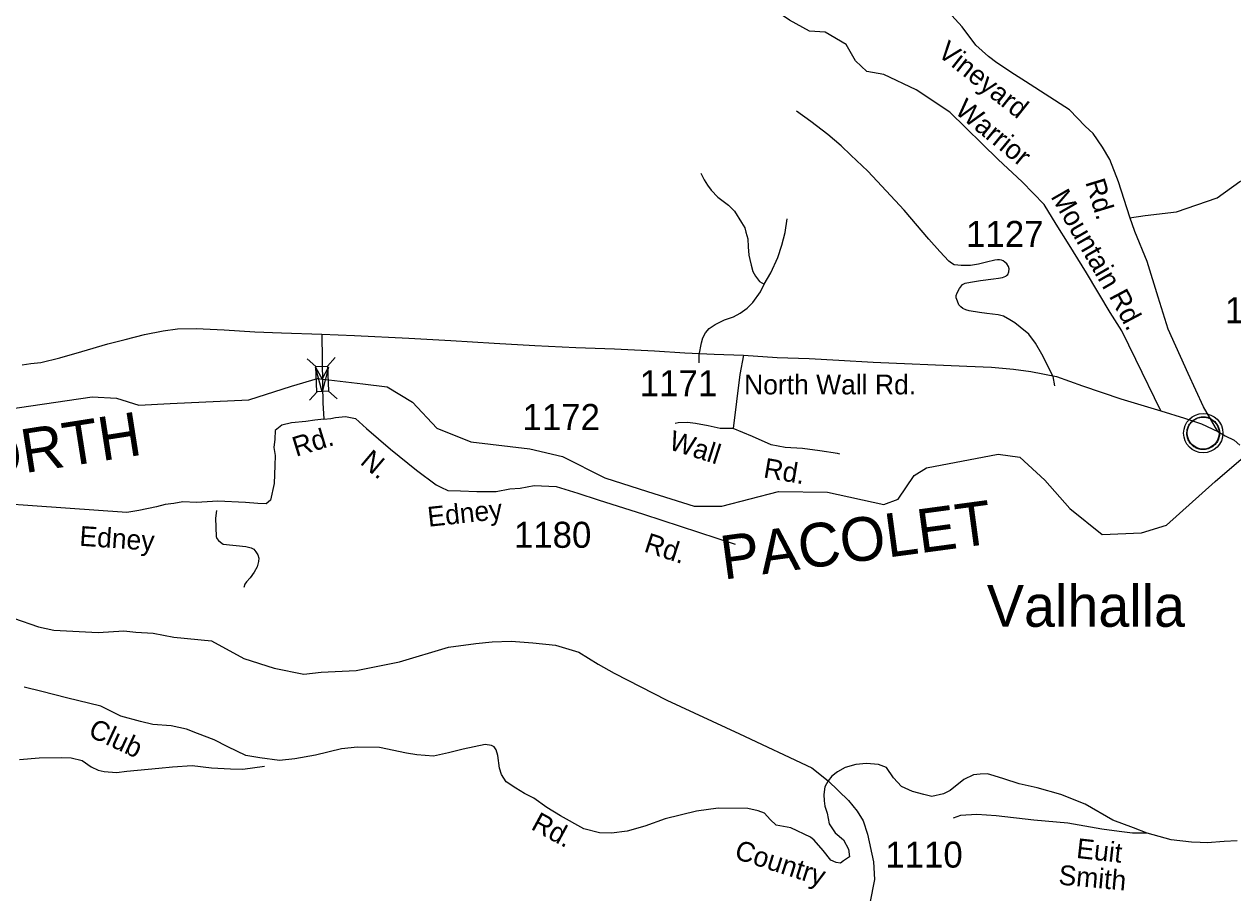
# Model space of a CAD drawing. Extents: x 990631 to 1056237, y 535999 to 585651.
# Drawn here: x 1021960 to 1027764, y 550123 to 554294 of the extents above; entities that cross this region are included whole.
import ezdxf

# ---------------------------------------------------------------- set-up
doc = ezdxf.new("R2010")
doc.units = 0
for name, color, linetype in [('Exist Civil Demographics Community CELL', 7, 'Continuous'), ('Exist Civil Demographics Community Label', 7, 'Continuous'), ('Exist Hydrographic River Shore', 7, 'Continuous'), ('Exist Hydrographic River Shore Label', 7, 'Continuous'), ('Exist Railroad Mainline', 7, 'Continuous'), ('Exist Road Non-System Type 51', 7, 'Continuous'), ('Exist Road Primary US Attributed', 7, 'Continuous'), ('Exist Road Secondary Structure Standard Bridge Attributed CELL', 7, 'Continuous'), ('Exist Road Secondary Structure Standard Bridge CELL', 7, 'Continuous'), ('Exist Road Secondary Type 41 Attributed', 7, 'Continuous'), ('Exist Road Secondary Type 51 Attributed', 7, 'Continuous'), ('Exist Road Secondary Type 51 Label', 7, 'Continuous'), ('Exist Road Secondary Type 51 Number Label', 7, 'Continuous')]:
    doc.layers.add(name, color=color, linetype=linetype)

msp = doc.modelspace()

# ---------------------------------------------------------------- linework, layer by layer
at = {"layer": 'Exist Civil Demographics Community CELL'}
msp.add_lwpolyline([(1027544.6, 552342.9), (1027545.6, 552348.5), (1027547.4, 552355.1), (1027550.3, 552362.3), (1027553.2, 552368), (1027556.5, 552373.8), (1027560.3, 552378.9), (1027564.3, 552383.3), (1027568.9, 552387.9), (1027574.4, 552392.4), (1027579.8, 552396.1), (1027584.7, 552399), (1027589.7, 552401.4), (1027595.2, 552403.7), (1027600.8, 552405.5), (1027605.2, 552406.7), (1027610, 552407.4), (1027614.1, 552408.1), (1027620.5, 552408.4), (1027624.9, 552408.3), (1027630.6, 552408), (1027635.5, 552407.3), (1027640.4, 552406.3), (1027645.4, 552404.9), (1027650.6, 552403), (1027657.2, 552400.1), (1027663.5, 552396.6), (1027668.6, 552393), (1027673.7, 552389), (1027677, 552385.9), (1027681.2, 552381.5), (1027685, 552376.8), (1027688.1, 552372.2), (1027691.2, 552367.2), (1027693.7, 552362), (1027695.7, 552357), (1027697.3, 552352), (1027698.6, 552347.4), (1027699.7, 552341.4), (1027700.3, 552336.7), (1027700.5, 552330.7), (1027700.4, 552324.9), (1027699.8, 552319.2), (1027698.9, 552313.7), (1027697.2, 552307.5), (1027695.3, 552301.7), (1027693, 552296.6), (1027689.9, 552290.6), (1027686.6, 552285.3), (1027683.1, 552280.6), (1027678.9, 552275.9), (1027673.6, 552270.9), (1027668.6, 552266.8), (1027663.6, 552263.4), (1027659.3, 552260.8), (1027652.5, 552257.6), (1027645.3, 552254.9), (1027639.4, 552253.4), (1027632.8, 552252.1), (1027628.3, 552251.7), (1027623.8, 552251.4), (1027618.3, 552251.4), (1027614, 552251.8), (1027608.3, 552252.6), (1027602.4, 552253.9), (1027597.8, 552255.2), (1027592.7, 552257), (1027588.1, 552259), (1027584.2, 552261.3), (1027577.4, 552265.3), (1027571.8, 552269.6), (1027566.9, 552274.1), (1027562.4, 552279), (1027559.2, 552282.9), (1027556.2, 552287.1), (1027552.2, 552294.2), (1027550.4, 552297.7), (1027548.7, 552301.8), (1027546.1, 552309.9), (1027544.6, 552317), (1027543.9, 552322.2), (1027543.6, 552328.5), (1027543.5, 552333.2), (1027544.1, 552339.6)], close=True, dxfattribs=at)
for centre, radius in [((1027622.2, 552330.5), 94.3), ((1027621.9, 552330.8), 76.7)]:
    msp.add_circle(centre, radius, dxfattribs=at)
at = {"layer": 'Exist Hydrographic River Shore'}
msp.add_lwpolyline([(1021815.9, 552435.4), (1022286.2, 552505.3), (1022403.7, 552497.9), (1022510.3, 552464.8), (1022660.9, 552472.2), (1023038.3, 552490.4), (1023244, 552556.6), (1023368.9, 552593.3), (1023585.7, 552567.6), (1023703.3, 552552.9), (1023824.5, 552479.4), (1023942.1, 552354.4), (1024105, 552288.9), (1024387.9, 552255.8), (1024545.9, 552219), (1024747.9, 552116.1), (1024953.7, 552049.9), (1025177.8, 551980), (1025310, 551980), (1025581.9, 552049.9), (1025817.1, 552046.2), (1026088.9, 551987.4), (1026156.6, 552013), (1026233.7, 552127), (1026292.5, 552163.7), (1026637.9, 552229.9), (1026740.7, 552215.2), (1026862, 552104.9), (1026981.7, 551969), (1027137.5, 551843.9), (1027324.9, 551851.2), (1027446, 551888.3), (1027679.8, 552097.4), (1027837.9, 552233.8)], dxfattribs=at)
at = {"layer": 'Exist Railroad Mainline'}
msp.add_lwpolyline([(1021908.7, 551441.8), (1022028.9, 551400.3), (1022102.4, 551383.8), (1022314.6, 551372.5), (1022438.9, 551380.4), (1022496, 551374), (1022579.6, 551369.8), (1022677.9, 551350.8), (1022859.3, 551332.5), (1023014.4, 551248.5), (1023160.7, 551202.5), (1023303.1, 551173.8), (1023386.7, 551182.1), (1023453.6, 551186.3), (1023553.9, 551190.5), (1023762.9, 551232.3), (1023997, 551303.4), (1024128.7, 551320.2), (1024207, 551327.6), (1024299.4, 551331.1), (1024402.5, 551324.3), (1024511.2, 551311.8), (1024624.1, 551278.3), (1024716, 551221.9), (1024792.5, 551177.3), (1025046.3, 551048.3), (1025395.1, 550886.9), (1025742.1, 550723.8), (1025820.3, 550661.4), (1025919.2, 550567.1), (1025959.5, 550514.7), (1025988.7, 550468.7), (1026009.8, 550404.2), (1026038.9, 550272.2), (1026043.7, 550186.8), (1026021.4, 550073.6)], dxfattribs=at)
at = {"layer": 'Exist Road Non-System Type 51'}
for points in [[(1026088.4, 554052.2), (1026006.9, 554067.3), (1025952.6, 554117.5), (1025906.6, 554196.9), (1025806.3, 554255.5), (1025731, 554259.7), (1025634.9, 554314), (1025547.1, 554372.6), (1025450.9, 554401.9), (1025400.8, 554460.4), (1025300.5, 554535.7), (1025250.3, 554590), (1025183.4, 554627.7), (1025120.7, 554627.7), (1025053.8, 554627.7), (1024953.5, 554619.3), (1024895, 554640.2), (1024731.9, 554769.9), (1024628.3, 554828.4)], [(1026910, 552557.5), (1026901.5, 552601.7), (1026847.1, 552709.6), (1026816.9, 552762.6), (1026784.2, 552805.7), (1026743.3, 552839.2), (1026718.1, 552860.1), (1026692.6, 552875), (1026663.1, 552892), (1026637.2, 552898.7), (1026583.3, 552904.6), (1026547.6, 552909.7), (1026497.8, 552917.3), (1026481.9, 552922.1), (1026468.2, 552928.3), (1026458.4, 552936.7), (1026448.8, 552947.1), (1026441.3, 552963.3), (1026435.8, 552979.6), (1026436.2, 552991.6), (1026440.7, 553003.3), (1026451.3, 553025.1), (1026465.9, 553044.6), (1026478.2, 553050.2), (1026504.4, 553055.2), (1026552.7, 553063.7), (1026615.1, 553071.6), (1026639.2, 553074.7), (1026657.3, 553078.2), (1026673.4, 553083.6), (1026677.7, 553087.6), (1026683.7, 553091.4), (1026688.2, 553105.1), (1026690.7, 553119.1), (1026687.1, 553131.2), (1026679.4, 553143.5), (1026669.7, 553151.9), (1026661.9, 553158.1), (1026653.9, 553160.5), (1026644.2, 553162.7), (1026634.2, 553163.1), (1026621.9, 553161.5), (1026581.7, 553150.7), (1026543.3, 553142.1), (1026505, 553135.3), (1026458.9, 553134.8), (1026443.2, 553137.3), (1026425.2, 553138.1), (1026413.4, 553146.3), (1026399.8, 553156.8), (1026357.3, 553202.3), (1026305.1, 553262.1), (1026185.6, 553400.2), (1026056.4, 553540.6), (1026011.8, 553588.2), (1025930.3, 553664.8), (1025883.8, 553710.4), (1025819.7, 553764.7), (1025737.7, 553827.4), (1025669.2, 553875.8)], [(1025209.1, 553578.9), (1025225.9, 553546.2), (1025241.2, 553521.7), (1025258.3, 553497.1), (1025291.2, 553464.1), (1025341.9, 553424.2), (1025371.1, 553395.4), (1025405.2, 553342.1), (1025420.5, 553315.6), (1025425.7, 553295.5), (1025434.6, 553263.1), (1025437.5, 553225), (1025440.1, 553185), (1025445.5, 553164.6), (1025450.5, 553136.5), (1025459.5, 553106.1), (1025472.6, 553083.7), (1025491.9, 553059.1), (1025513.5, 553046.4)], [(1027267.2, 553363.5), (1027342.5, 553376), (1027493, 553392.8), (1027689.4, 553459.7), (1027798.1, 553539.1), (1027890.1, 553576.8), (1027948.6, 553547.5), (1027983.1, 553530.4)], [(1025513.5, 553046.4), (1025545.4, 553099.4), (1025579.9, 553174.1), (1025597.7, 553233.6), (1025613.7, 553293.1), (1025624, 553358.9)], [(1025200.8, 552668.4), (1025202, 552706.4), (1025211.9, 552764.2), (1025218.6, 552788.1), (1025231.5, 552811.6), (1025250.1, 552833.1), (1025278.9, 552852.1), (1025323.6, 552874.6), (1025366.1, 552889.2), (1025398.6, 552906.1), (1025431.5, 552931), (1025458.5, 552958.1), (1025496.1, 553009), (1025513.5, 553046.4)], [(1022883.6, 551959.3), (1022878.3, 551921.4), (1022881.3, 551833.4), (1022885.1, 551825.1), (1022892.7, 551814.9), (1022902.6, 551806.5), (1022916.2, 551798), (1023024, 551786.5), (1023049.7, 551779.7), (1023063.5, 551773.3), (1023073.1, 551760.9), (1023082.6, 551746.5), (1023086.1, 551730.4), (1023085.6, 551714.4), (1023078.6, 551688.7), (1023063.7, 551663), (1023045, 551635.8), (1023028.2, 551616.3), (1023019.9, 551604.5), (1023015.2, 551588.6)], [(1021937.1, 550764.1), (1022031.4, 550771), (1022137.5, 550773.4), (1022185.5, 550771.8), (1022239, 550758), (1022282.1, 550728.5), (1022315.5, 550711.4), (1022343.4, 550706.4), (1022403.3, 550700.4), (1022453.5, 550706.8), (1022606.2, 550721.7), (1022672.4, 550727.6), (1022766.7, 550734.3), (1022860.3, 550723.2), (1022950.2, 550718.2), (1023010.2, 550716.2), (1023114.7, 550730.7)]]:
    msp.add_lwpolyline(points, dxfattribs=at)
at = {"layer": 'Exist Road Primary US Attributed'}
for points in [[(1021949.8, 552657.6), (1021991.3, 552664.5), (1022039.7, 552670), (1022131.1, 552692.2), (1022236.3, 552722.7), (1022362.3, 552758.7), (1022445.3, 552779.4), (1022538.5, 552804.1), (1022628, 552820.8), (1022696.4, 552830.5), (1022785.9, 552832.2), (1022920.1, 552826.1), (1023066.9, 552816.8), (1023195.6, 552811.3), (1023389.4, 552805.1)], [(1023389.4, 552805.1), (1023545.9, 552798.8), (1023807.5, 552786.4), (1024008.2, 552775.3), (1024217.6, 552761.6), (1024411.5, 552751.9), (1024609.8, 552741.8), (1024794.5, 552735.1), (1024986.9, 552725.4), (1025132.3, 552715.7), (1025273.9, 552709.3), (1025414.3, 552705)], [(1025414.3, 552705), (1025575.3, 552693.6), (1025730.3, 552688), (1025872.9, 552681.1), (1026037.6, 552671.4), (1026486.1, 552652), (1026605.2, 552646.5), (1026710.4, 552638.2), (1026793.4, 552627.1), (1026918, 552602.1), (1027042.6, 552557.9), (1027226.7, 552495.5), (1027418.2, 552437.4)], [(1027418.2, 552437.4), (1027531.3, 552402.7), (1027614.3, 552375), (1027691.9, 552337.6)], [(1027691.9, 552337.6), (1027727.9, 552316.8), (1027770.8, 552296), (1027798, 552272.6)]]:
    msp.add_lwpolyline(points, dxfattribs=at)
at = {"layer": 'Exist Road Secondary Structure Standard Bridge Attributed CELL'}
msp.add_lwpolyline([(1023422, 552646.7), (1023390.5, 552528.9), (1023358.9, 552646.7), (1023390.5, 552589.9)], close=True, dxfattribs=at)
at = {"layer": 'Exist Road Secondary Structure Standard Bridge CELL'}
for p, q in [((1023319.2, 552686.8), (1023360, 552649.7)), ((1023453.6, 552693.1), (1023416.4, 552652.3)), ((1023366.7, 552529), (1023329.6, 552488.1)), ((1023421.8, 552531.5), (1023462.7, 552494.4))]:
    msp.add_line(p, q, dxfattribs=at)
msp.add_lwpolyline([(1023416.4, 552652.3), (1023422.1, 552531.6), (1023365.7, 552528.9), (1023360, 552649.7)], close=True, dxfattribs=at)
at = {"layer": 'Exist Road Secondary Type 41 Attributed'}
for points in [[(1023389.4, 552805.1), (1023392.5, 552560.9)], [(1023392.5, 552560.9), (1023393.6, 552476.1), (1023399.1, 552396.9)], [(1023399.1, 552396.9), (1023356.3, 552392.1), (1023311.9, 552386.9), (1023244.1, 552379.1), (1023197.2, 552368.6), (1023165.9, 552342.5), (1023163.3, 552300.8), (1023158.1, 552261.6), (1023165.9, 552222.5), (1023163.3, 552175.5), (1023160.1, 552088.2), (1023143.3, 552008.7), (1023121.6, 551990.3), (1023082.5, 551992.9), (1023022.5, 551998.1), (1022889.5, 552003.3), (1022787.8, 551998.1), (1022722.6, 552000.7), (1022678.3, 551992.9), (1022636.6, 551987.7), (1022595.9, 551977), (1022511.3, 551959.7), (1022452.9, 551949.6), (1021410, 552022.9)], [(1027353.4, 550409), (1027282.6, 550409.1), (1027218.8, 550417.2), (1027135.2, 550428.1), (1027053.6, 550442.7), (1026971.9, 550457.4), (1026808.4, 550472.9), (1026626.9, 550492.9), (1026535, 550500), (1026456.9, 550494.6), (1026420.4, 550481.9)]]:
    msp.add_lwpolyline(points, dxfattribs=at)
at = {"layer": 'Exist Road Secondary Type 51 Attributed'}
for points in [[(1027691.9, 552337.6), (1027623.2, 552457.2), (1027549.4, 552616.6), (1027453.1, 552829.1), (1027404.9, 552982.9), (1027352.4, 553153.7), (1027293.3, 553298.2), (1027270.3, 553367.2), (1027214.5, 553536.4), (1027173.4, 553644.8), (1027139, 553704), (1027093, 553769.7), (1027055.2, 553804.2), (1026979.7, 553883), (1026768, 554019.3), (1026715.4, 554052.2), (1026631.6, 554107.8), (1026590.6, 554139.3), (1026529.9, 554193.4), (1026464.3, 554280.5), (1026364.1, 554392.2)], [(1027418.2, 552437.4), (1027298.7, 552683.9), (1027230.9, 552821), (1027175.9, 552909.8), (1027061, 553100.3), (1026978.9, 553235), (1026916.5, 553333.6), (1026858.3, 553428), (1026753.2, 553536.4), (1026636.6, 553644.8), (1026405.2, 553871.5), (1026242.7, 553978.3), (1026088.4, 554052.2)], [(1025414.3, 552705), (1025396.9, 552611.8), (1025364.1, 552353)], [(1023399.1, 552396.9), (1023431.9, 552399.9), (1023455.3, 552405.1), (1023502.3, 552410.4), (1023551.8, 552399.9), (1023604, 552353), (1023718.7, 552253.8), (1023843.9, 552152.1), (1023937.7, 552081.6), (1023961.2, 552071.2), (1023995.1, 552055.5), (1024055.1, 552052.9), (1024133.3, 552050.3), (1024227.2, 552050.3), (1024292.4, 552063.3), (1024341.9, 552066), (1024409.7, 552079), (1024514, 552073.8), (1024618.3, 552042.5), (1024716.4, 552010.2), (1024934.3, 551941), (1025374.3, 551798)], [(1025364.1, 552353), (1025301.5, 552353), (1025244.1, 552366), (1025184.1, 552376.4), (1025145, 552381.7), (1025100.7, 552379.1), (1025085.6, 552376.3)], [(1025876.8, 552230.1), (1025866.3, 552232), (1025781.3, 552246), (1025697.8, 552256.4), (1025614.4, 552261.6), (1025546.6, 552274.7), (1025457.9, 552313.8), (1025364.1, 552353)], [(1022666.2, 550925.3), (1022577.7, 550931), (1022518, 550945.8), (1022424.8, 550971.3), (1022328.2, 551019), (1022163.9, 551059.2), (1022044.3, 551090.3), (1021959.3, 551110.4)], [(1025820.3, 550661.4), (1025804.2, 550631.5), (1025800.8, 550595.8), (1025801.7, 550565.6), (1025805.3, 550539.8), (1025815.9, 550505), (1025825.1, 550455.2), (1025854.6, 550410.9), (1025895.1, 550377.3), (1025919.1, 550333.4), (1025922.8, 550296.5), (1025895.2, 550276.2), (1025880.4, 550265.2), (1025859.4, 550268.1), (1025833, 550280.7), (1025797.3, 550326.7), (1025753.7, 550376.2), (1025736.4, 550391.1), (1025642, 550434.6), (1025570.9, 550448.6), (1025542.2, 550475.1), (1025514.6, 550505), (1025484.7, 550516.5), (1025435.3, 550527.4), (1025292.7, 550529.7), (1025188.1, 550515.9), (1025037.5, 550479.1), (1024941, 550442.9), (1024855.9, 550419.9), (1024781.2, 550409.5), (1024722.6, 550411.8), (1024647.2, 550431.2), (1024535.2, 550492.9), (1024469.7, 550533.1), (1024406.8, 550578.4), (1024362.6, 550600.5), (1024321.4, 550625.7), (1024274.3, 550655.6), (1024252.7, 550691.3), (1024243.3, 550722.3), (1024235.2, 550782.7), (1024226, 550810.3), (1024216.8, 550824.7), (1024203.9, 550830.3), (1024173.4, 550835.1), (1024068.5, 550813.1), (1023998.4, 550795.9), (1023926.2, 550780), (1023845.1, 550785.5), (1023796.1, 550794.2), (1023666.2, 550821.2), (1023560.5, 550822.3), (1023483.5, 550815.4), (1023359.3, 550783.8), (1023260.5, 550766.6), (1023185.7, 550758.5), (1023091.3, 550770.6), (1023023.7, 550783.2), (1022938.6, 550823.5), (1022871.9, 550858), (1022792.6, 550889), (1022739.8, 550909.7), (1022666.2, 550925.3)], [(1027353.4, 550409), (1027287.6, 550435.4), (1027187.4, 550471.8), (1027054.7, 550549.2), (1026938.5, 550595.4), (1026824.2, 550626.7), (1026737.6, 550647), (1026663.9, 550671), (1026617.8, 550685.7), (1026586.4, 550695), (1026551.4, 550693.1), (1026518.2, 550689.4), (1026472.2, 550667.3), (1026406.9, 550614.8), (1026374.4, 550597.9), (1026319.2, 550586.1), (1026280.4, 550595.4), (1026225.1, 550610.1), (1026173.5, 550634.1), (1026134.8, 550674.7), (1026101.6, 550724.5), (1026062.9, 550739.2), (1026005.6, 550744.7), (1025953.9, 550739.1), (1025903.1, 550724.6), (1025865.2, 550703.9), (1025838.7, 550683.2), (1025820.3, 550661.4)], [(1027784.7, 550372.2), (1027722, 550370.3), (1027641.4, 550363.6), (1027607.4, 550364.7), (1027565.3, 550366.6), (1027467.3, 550377.9), (1027353.4, 550409)]]:
    msp.add_lwpolyline(points, dxfattribs=at)

# ---------------------------------------------------------------- texts
at = {"layer": 'Exist Civil Demographics Community Label'}
msp.add_text('Valhalla', height=200, dxfattribs=at).set_placement((1026583.1, 551400.7))
at = {"layer": 'Exist Hydrographic River Shore Label'}
for s, rotation, p in [('NORTH', 8.90661, (1021546.4, 552072.7)), ('PACOLET', 7.67547, (1025318.8, 551626.5))]:
    msp.add_text(s, height=210, rotation=rotation, dxfattribs=at).set_placement(p)
at = {"layer": 'Exist Road Secondary Type 51 Label'}
for s, rotation, p in [('Vineyard', 321.58579, (1026340.6, 554147)), ('Warrior', 320.52111, (1026424.3, 553870.2)), ('Rd.', 286.98611, (1027055.1, 553535.9)), ('Mountain', 299.87406, (1026887.4, 553466.5)), ('Rd.', 298.01531, (1027167.7, 552989)), ('Rd.', 17.08161, (1023265.3, 552216.4)), ('Wall', 342.35031, (1025050.3, 552254.5)), ('N.', 319.75932, (1023568.7, 552185.7)), ('Rd.', 350.29371, (1025506.2, 552118.2)), ('Edney', 6.15578, (1023901.9, 551880.6)), ('Edney', 355.9815, (1022223.2, 551790.2)), ('Rd.', 342.00425, (1024931.6, 551762.9)), ('Club', 335.14057, (1022262.3, 550877.5)), ('Rd.', 331.50521, (1024389, 550431.3)), ('Country', 342.24997, (1025365.7, 550289.3)), ('Euit', 353.68875, (1027009.6, 550291.2)), ('Smith', 354.9043, (1026924.6, 550163))]:
    msp.add_text(s, height=95, rotation=rotation, dxfattribs=at).set_placement(p)
msp.add_text('North Wall Rd.', height=95, dxfattribs=at).set_placement((1025417.3, 552516.4))
at = {"layer": 'Exist Road Secondary Type 51 Number Label'}
for s, p in [('1127', (1026483.4, 553224.2)), ('1125', (1027726.1, 552858.2)), ('1171', (1024916.4, 552507.5)), ('1172', (1024353, 552345.4)), ('1180', (1024311.8, 551779.8)), ('1110', (1026095.3, 550244.3))]:
    msp.add_text(s, height=125, dxfattribs=at).set_placement(p)

doc.saveas('drawing.dxf')
